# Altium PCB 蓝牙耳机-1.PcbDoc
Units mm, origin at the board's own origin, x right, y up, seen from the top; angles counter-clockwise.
Board outline 16.51 x 36.18 mm, 2 copper layers (Top Layer, Bottom Layer); 36 components, 36 nets, 115 pads, 134 vias.
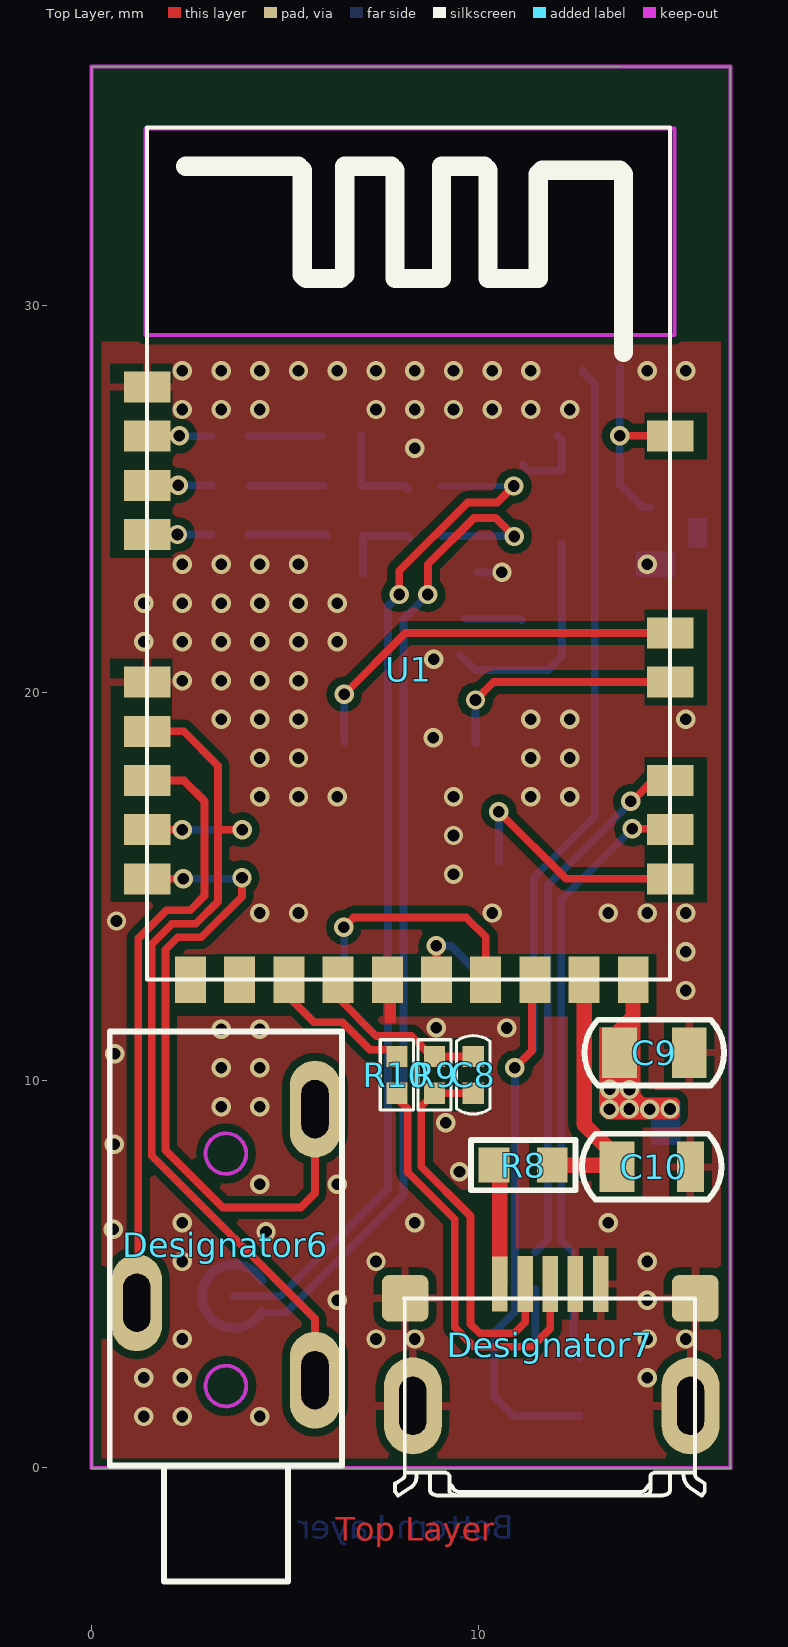
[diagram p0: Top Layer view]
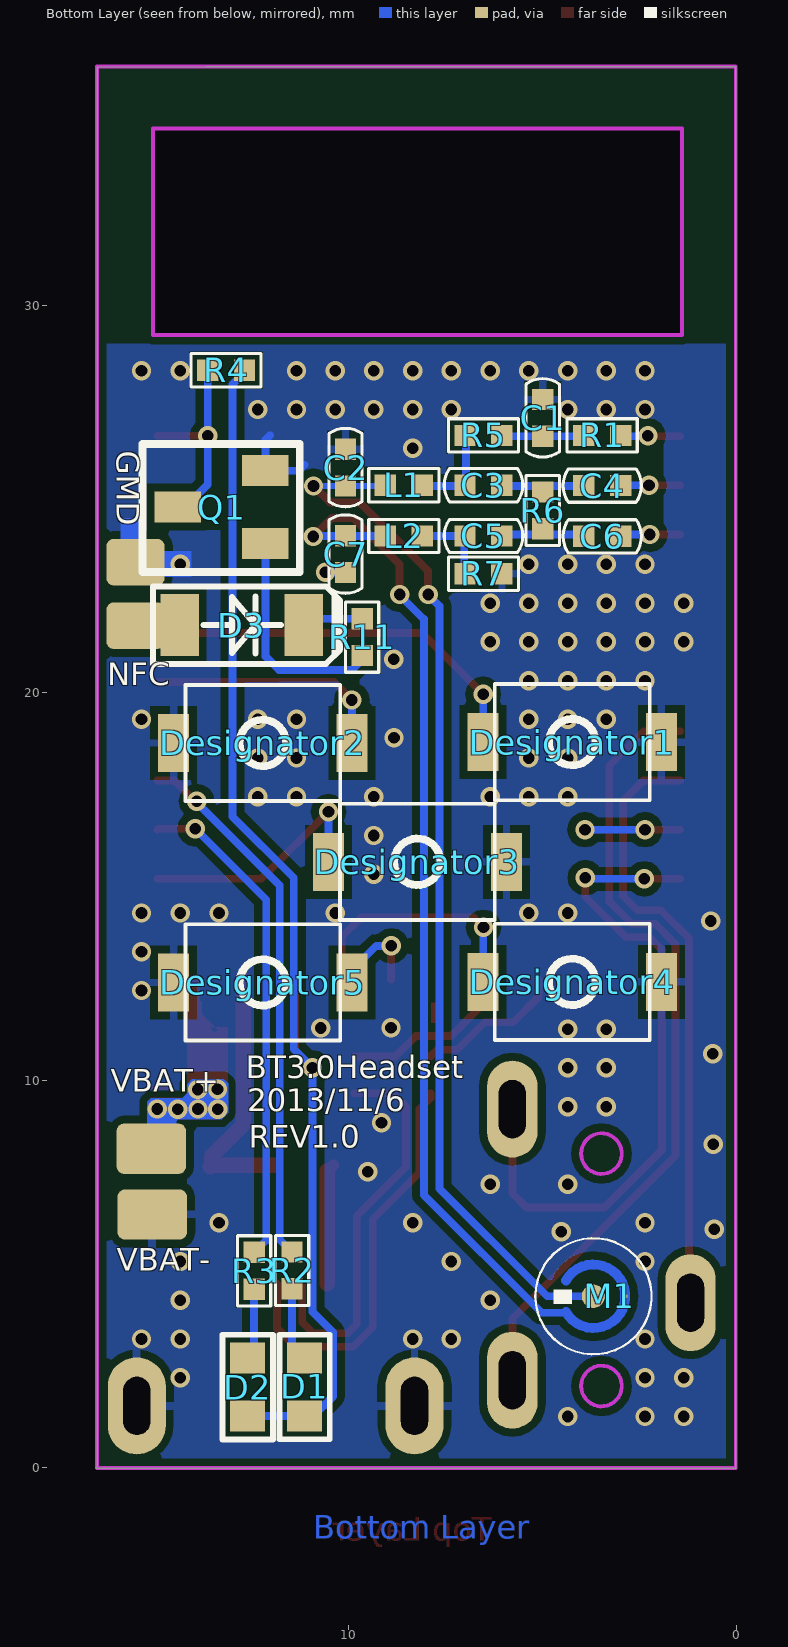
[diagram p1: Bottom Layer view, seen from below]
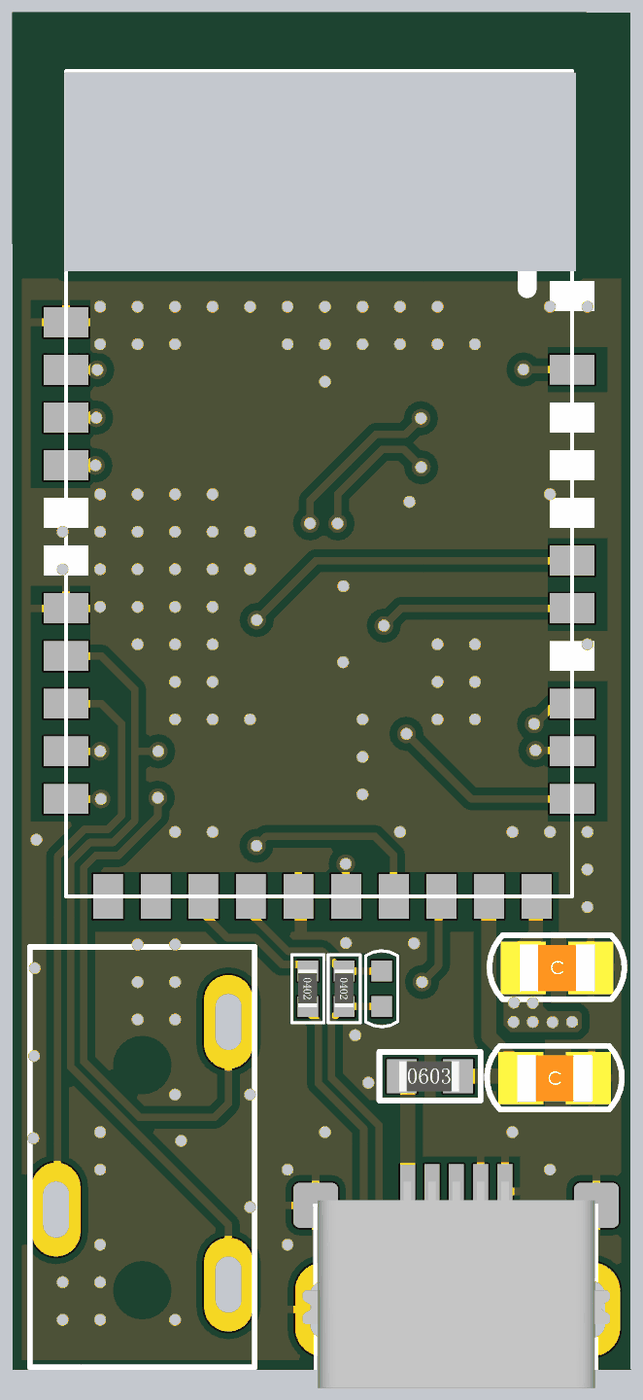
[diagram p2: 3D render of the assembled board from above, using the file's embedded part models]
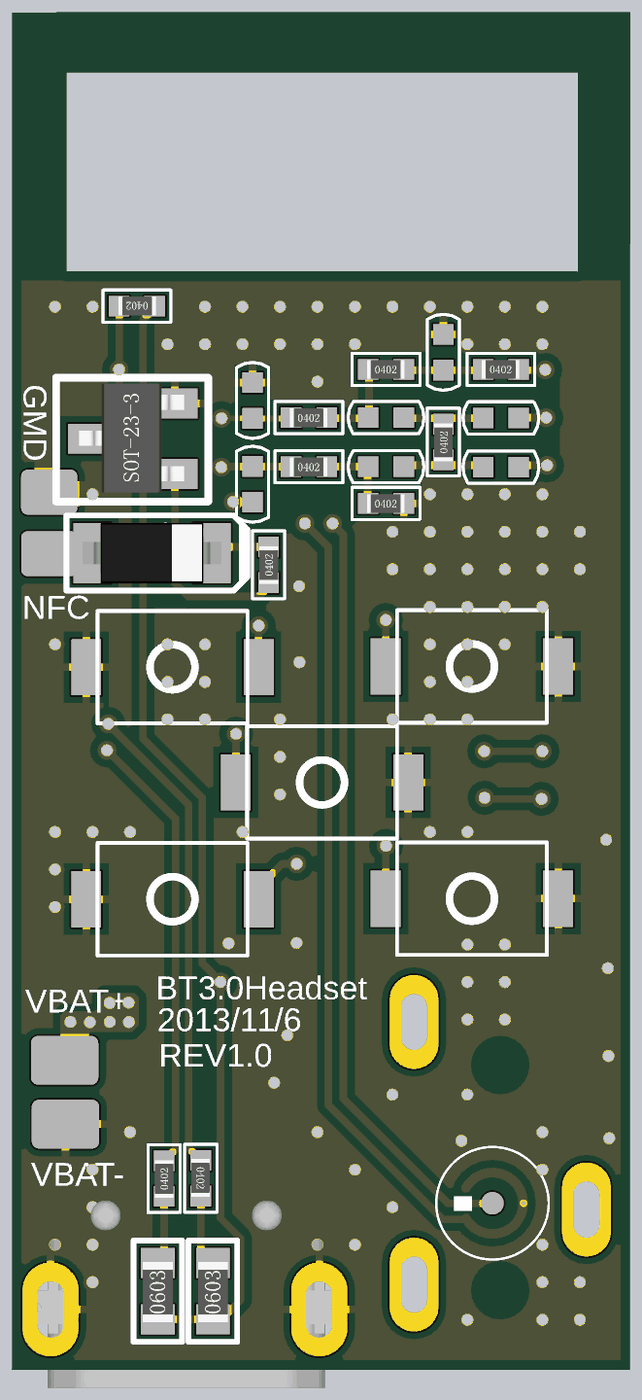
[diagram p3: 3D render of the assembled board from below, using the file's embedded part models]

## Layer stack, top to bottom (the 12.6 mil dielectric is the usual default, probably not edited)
Top Solder: solder mask 0.0102, Solder Resist, Dk 3.5
Top Layer: signal copper 0.0356
Dielectric1: dielectric 0.32, FR-4, Dk 4.8
Bottom Layer: signal copper 0.0356
Bottom Solder: solder mask 0.0102, Solder Resist, Dk 3.5

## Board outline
13.687,36.165 0.006,36.166 0.01,29.208 0.01,-0.019 16.506,-0.019 16.52,-0.005 16.492,0.023 16.494,36.156
cut-out: 15.045,34.559 1.406,34.559 1.388,34.542 1.406,34.524 1.406,29.234 1.428,29.256 15.054,29.256 15.049,29.261 15.049,34.551

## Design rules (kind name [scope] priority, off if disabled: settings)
Clearance "Stitching GND" [IsStitchingVia and InNet('GND') vs (IsVia and (Not IsStitchingVia)) Or IsPad] p1: gap=0.127
Clearance Clearance_1 [InPolygon] p2: gap=0.2
Clearance [All] p3: gap=0.15
PolygonConnect PolygonConnect_1 [IsVia] p1: connectstyle=Direct reliefconductorwidth=0.254 reliefentries=4 polygonreliefangle="90 Angle" airgapwidth=0.254
PolygonConnect [All] p2: connectstyle=Relief reliefconductorwidth=0.2 reliefentries=4 polygonreliefangle="90 Angle" airgapwidth=0.2
RoutingVias [All] p1: holewidth=0.3 width=0.5 viastyle="Through Hole" minholewidth=0.3 minwidth=0.5 maxholewidth=0.3 maxwidth=0.5
SolderMaskExpansion [All] p1: expansion=0.05
Width [All] p1: maxlimit=3 minlimit=0.1 preferedwidth=0.2
29 further rules are at their usual default settings.

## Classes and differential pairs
component class Sheet1: BT1 C1 C2 C3 C4 C5 C6 C7 C8 C9 D1 D2 D3 L1 L2 Q1 R1 R2 R3 R4 R5 R6 R7 R8 R9 R10 R11 U1

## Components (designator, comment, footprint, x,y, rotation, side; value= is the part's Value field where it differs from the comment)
C1 "2.2UF" 0402C 4.994,27.101 r90 bottom
C2 "100PF" 0402C 10.084,25.818 r270 bottom
C3 "0.1U" 0402C 6.521,25.362 r180 bottom
C4 "0.022U" 0402C 3.456,25.352 r180 bottom
C5 "0.1U" 0402C 6.521,24.051 r180 bottom
C6 "0.022U" 0402C 3.456,24.041 r180 bottom
C7 "100PF" 0402C 10.084,23.585 r270 bottom
C8 "1UF" 0402C 9.861,10.138 r270 top
C9 "10UF" 0805C#1 14.537,10.712 r0 top
C10 "10UF" 0805C#2 14.471,7.768 r0 top
D1 "BLED" 0603 11.141,2.079 r90 bottom
D2 "RLED" 0603 12.61,2.077 r90 bottom
D3 "1N5817" SOD123 12.764,21.75 r180 bottom
Designator1 "Comment" SW-SMD-2 4.229,18.728 r0 bottom
Designator2 "Comment" SW-SMD-2 12.219,18.708 r180 bottom
Designator3 "Comment" SW-SMD-2 8.229,15.638 r0 bottom
Designator4 "Comment" SW-SMD-2 4.229,12.539 r0 bottom
Designator5 "Comment" SW-SMD-2 12.219,12.525 r180 bottom
Designator6 "Comment" jack-3 3.475,0.054 r90 top
Designator7 "Comment" "Micro USB-B" 11.891,2.328 r180 top
L1 "15NH" 0402 8.579,25.362 r180 bottom
L2 "15NH" 0402 8.579,24.051 r180 bottom
M1 "" MIC3 3.681,4.422 r0 bottom
Q1 "2N3904" SOT-23 13.281,24.798 r90 bottom
R1 "100R" 0402 3.456,26.647 r180 bottom
R2 "1K" 0402 11.463,5.089 r270 bottom
R3 "1K" 0402 12.443,5.079 r90 bottom
R4 "10K" 0402 13.169,28.332 r0 bottom
R5 "1K" 0402 6.521,26.647 r180 bottom
R6 "100K" 0402 4.994,24.71 r90 bottom
R7 "1K" 0402 6.521,23.073 r180 bottom
R8 "2R" 0603 11.151,7.808 r0 top
R9 "5.1K" 0402 8.861,10.138 r270 top
R10 "5.1K" 0402 7.891,10.138 r270 top
R11 "1K" 0402 9.655,21.439 r90 bottom
U1 "BCM20771" BT2771 1.442,34.598 r0 top locked

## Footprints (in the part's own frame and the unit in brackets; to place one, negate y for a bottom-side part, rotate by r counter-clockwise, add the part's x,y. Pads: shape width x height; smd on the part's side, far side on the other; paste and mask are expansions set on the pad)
0402 [mm]
  rect 0.55x0.55 smd: 1(-0.475,0) 2(0.475,0)
  silkscreen extent -0.9,-0.43 0.9,0.43, body extent -0.51,-0.25 0.49,0.25, height 0.35
0402C [mm]
  rect 0.55x0.55 smd: 1(-0.475,0) 2(0.475,0)
  silkscreen extent -1.01,-0.43 1.01,0.43, body extent -0.47,-0.28 0.49,0.27, height 0.5
0603 [mm]
  rect 0.8x0.9 smd: 1(-0.75,0) 2(0.75,0)
  silkscreen extent -1.35,-0.65 1.35,0.65, body extent -0.82,-0.4 0.78,0.4, height 0.45
0805C#1 [mm]
  rect 0.9x1.3 smd: 1(-0.9,0) 2(0.9,0)
  silkscreen extent -1.8,-0.85 1.8,0.85, body extent -1.49,-0.72 1.51,0.68, height 0.93
0805C#2 [mm]
  rect 0.9x1.3 smd: 1(-0.9,0)
  rect 0.7x1.3 smd: 2(0.995,-0.007)
  silkscreen extent -1.8,-0.85 1.8,0.85, body extent -1.49,-0.72 1.51,0.68, height 0.93
BT2771 [mm] "U?"
  rect 1.2x0.8 smd mask+0.05: 1(0,-6.7) 2(0,-7.97) 3(0,-9.24) 4(0,-10.51) 7(0,-14.32) 8(0,-15.59) 9(0,-16.86) 10(0,-18.13) 11(0,-19.4) 22(13.5,-19.4) 23(13.5,-18.13) 24(13.5,-16.86) 26(13.5,-14.32) 27(13.5,-13.05) 31(13.5,-7.96)
  rect 1.2x0.8 on Top Overlay mask+0.05: 5(0,-11.78) 6(0,-13.05) 25(13.5,-15.59) 28(13.5,-11.78) 29(13.5,-10.51) 30(13.5,-9.24) 32(13.5,-6)
  rect 0.8x1.2 smd mask+0.05: 12(1.12,-22) 13(2.39,-22) 14(3.66,-22) 15(4.93,-22) 16(6.2,-22) 17(7.47,-22) 18(8.74,-22) 19(10.01,-22) 20(11.28,-22) 21(12.55,-22)
  silkscreen extent 0,-22 13.5,0
jack-3 [mm]
  oval 2.5x1.3 hole 0.7 slot 1.5 at 0 deg: 1(2.2,-2.3) 2(4.2,2.3) 3(9.2,-2.3)
  Keep-Out Layer circle w0.1: c8.05,0 r0.525
  Keep-Out Layer circle w0.1: c2.05,0 r0.525
  silkscreen extent -3,-3 11.2,3
MIC3 [mm]
  round 0.6 smd: 1(0,0)
  round 0.1 smd mask+0.05: 2(-0.83,0)
  Top Layer lines w0.254: 0.71,0.41 ccw(c0,0) 0.71,-0.41
  silkscreen extent -1.5,-1.5 1.5,1.5
"Micro USB-B" [mm]
  rrect30% 1.2x1.2 smd: 0(-3.7,-2.04) 1(3.79,-2.04)
  rect 0.4x1.42 smd: 1(1.34,-2.41)
  rect 0.4x1.45 smd: 2(0.69,-2.41) 3(0.04,-2.41) 4(-0.61,-2.41) 5(-1.26,-2.41)
  oval 1.5x2.5 hole 0.7 slot 1.5 at 90 deg: 5(-3.581,0.736) 5(3.589,0.736)
  silkscreen extent -3.95,-2.04 4.05,3.05, body extent -4.06,-2.67 4.14,2.83, height 2.4
SOD123 [mm]
  rect 1x1.6 smd: 1(-1.6,0) 2(1.6,0)
  silkscreen extent -2.29,-1 2.54,1, body extent -1.85,-0.8 1.85,0.8, height 1.27
SOT-23 [mm] "Q?"
  rect 0.8x1.2 smd: 1(-0.94,-1.13) 2(0.94,-1.13) 3(0,1.13)
  silkscreen extent -1.68,-2.02 1.63,2.04, body extent -1.43,-1.37 1.47,1.43, height 1.2
SW-SMD-2 [mm]
  rect 0.8x1.5 smd: 1(-2.3,0) 2(2.3,0)
  silkscreen extent -2,-1.5 2,1.5

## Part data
C1 C2 C3 C4 C5 C6 C7 C8 C9: library part CAP, "Capacitor"
D1 D2: library part LED
D3: library part D1, "Diode"
L1 L2: library part INDUCTOR2_1
M1: library part MICROPHONE1, "Microphone"
Q1: "NPN General Purpose Amplifier"
R1 R2 R3 R4 R5 R6 R7 R8 R9 R10 R11: library part R
U1: library part BT20771

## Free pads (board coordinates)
  rrect30% 1.5x1.2 smd far side: 0(15.506,21.733) 1(15.507,23.373)
  rrect30% 1.8x1.3 smd far side: 2(15.073,6.53) 3(15.096,8.231)

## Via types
v1: diameter 0.5, hole 0.3, Top Layer to Bottom Layer, tented both sides, 134 vias

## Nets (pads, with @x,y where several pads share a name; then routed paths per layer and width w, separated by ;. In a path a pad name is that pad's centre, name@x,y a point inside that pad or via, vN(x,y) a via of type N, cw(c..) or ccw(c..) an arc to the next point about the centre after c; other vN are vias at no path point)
GND: C1.2 C2.1 C7.2 C9.2 C10.2 Designator1.1 Designator2.1 Designator3.1 Designator4.1 Designator5.1 Designator7.0 Designator7.1@8.101,4.368 Designator7.4 Designator7.5 pad.1 pad.2 Q1.2 R7.2 U1.1 U1.7 U1.16 | length 2.7
  Bottom Layer w0.2: C7.2@9.974,23.11 10.596,23.11 v1(10.602,23.116) ; 11.144,25.888 11.294,25.738 Q1.2 12.151,26.536 12.035,26.652
  other v1: 1.35,1.317 2.35,1.317 4.35,1.317 1.35,2.317 2.35,2.317 14.35,2.317 2.35,3.317 7.35,3.317 8.35,3.317 14.35,3.317 15.35,3.317 6.35,4.317 14.35,4.317 2.35,5.317 7.35,5.317 14.35,5.317 4.51,6.087 0.566,6.154 2.35,6.317 8.35,6.317 13.35,6.317 4.35,7.317 6.35,7.317 9.506,7.633 0.589,8.347 9.155,8.898 3.35,9.317 4.35,9.317 3.35,10.317 4.35,10.317 0.604,10.686 3.35,11.317 4.35,11.317 8.909,11.358 10.723,11.348 15.35,12.317 15.35,13.317 0.65,14.109 4.35,14.317 5.35,14.317 10.35,14.317 13.35,14.317 14.35,14.317 15.35,14.317 9.35,15.317 9.35,16.317 4.35,17.317 5.35,17.317 6.35,17.317 9.35,17.317 11.35,17.317 12.35,17.317 4.35,18.317 5.35,18.317 11.35,18.317 12.35,18.317 8.832,18.842 3.35,19.317 4.35,19.317 5.35,19.317 11.35,19.317 12.35,19.317 15.35,19.317 2.35,20.317 3.35,20.317 4.35,20.317 5.35,20.317 8.84,20.868 1.35,21.317 2.35,21.317 3.35,21.317 4.35,21.317 5.35,21.317 6.35,21.317 1.35,22.317 2.35,22.317 3.35,22.317 4.35,22.317 5.35,22.317 6.35,22.317 2.35,23.317 3.35,23.317 4.35,23.317 5.35,23.317 14.35,23.317 8.35,26.317 2.35,27.317 3.35,27.317 4.35,27.317 7.35,27.317 8.35,27.317 9.35,27.317 10.35,27.317 11.35,27.317 12.35,27.317 2.35,28.317 3.35,28.317 4.35,28.317 5.35,28.317 6.35,28.317 7.35,28.317 8.35,28.317 9.35,28.317 10.35,28.317 11.35,28.317 14.35,28.317 15.35,28.317
LED1: R2.1 U1.24 | length 13.9
  Top Layer w0.2: v1@13.926,17.165 14.499,17.738 14.587,17.738 U1.24
  Bottom Layer w0.2: R2.1 11.783,5.883 11.783,15.028 13.924,17.169 v1@13.939,17.169
  other v1: 13.929,17.197
LED2: R3.2 U1.23 | length 12.8
  Top Layer w0.2: v1(13.965,16.492) 14.918,16.492 U1.23
  Bottom Layer w0.2: R3.2 12.133,5.864 12.133,14.66 v1(13.965,16.492)
M+: C2.2 L1.1 M1.1 | length 27
  Top Layer w0.2: v1@7.953,22.54 7.953,23.153 9.716,24.915 10.482,24.915 v1(10.91,25.343)
  Bottom Layer w0.15: L1.1@9.019,25.338 C2.2@9.978,25.338 ; C2.2@9.978,25.343 v1(10.91,25.343)
  Bottom Layer w0.2: M1.1 4.874,4.422 5.029,4.577 ; 5.032,4.575 7.66,7.202 7.66,22.243 v1@7.96,22.543
  other v1: 7.95,22.54
M-: C7.1 L2.1 M1.2 | length 26.3
  Top Layer w0.2: v1@8.69,22.535 8.69,23.324 9.881,24.515 10.439,24.515 v1(10.916,24.038)
  Bottom Layer w0.2: 4.392,4.043 4.392,4.012 4.392,3.995 4.393,3.993 5.016,3.993 8.06,7.037 8.06,21.904 v1@8.693,22.537 ; L2.1 v1@10.912,24.051
  other v1: 8.685,22.54
MIC+: C4.2 U1.3 | length 1.7
  Top Layer w0.2: U1.3 v1(2.248,25.358)
  Bottom Layer w0.2: v1(2.248,25.358) 2.251,25.362 C4.2@3.111,25.362
MIC-: C6.2 U1.4 | length 1.7
  Top Layer w0.2: U1.4 v1(2.227,24.088)
  Bottom Layer w0.2: v1@2.228,24.089 C6.2@3.111,24.089
MIC-BLAS: R1.2 U1.2 | length 1.7
  Top Layer w0.2: U1.2 2.269,26.628 v1(2.275,26.635)
  Bottom Layer w0.2: v1(2.275,26.635) 2.282,26.628 R1.2@3.106,26.628
NetC1_1: C1.1 R1.1 R5.2 | length 1.9
  Bottom Layer w0.2: R1.1@4.056,26.628 5.945,26.628 R5.2@5.948,26.624
NetC3_1: C3.1 L1.2 R5.1 | length 2.5
  Bottom Layer w0.2: R5.1@6.971,26.647 6.971,25.368 6.996,25.343 8.096,25.343 L1.2@8.175,25.265
NetC3_2: C3.2 C4.1 R6.2 | length 1.9
  Bottom Layer w0.15: C4.1@4.061,25.362 C4.1@4.08,25.343
  Bottom Layer w0.2: C4.1@4.08,25.343 C3.2@6.002,25.343
NetC5_1: C5.1 L2.2 R7.1 | length 2.2
  Bottom Layer w0.2: C5.1@6.983,24.018 7.015,23.987 R7.1@7.015,23.073 ; C5.1@7.015,24.051 8.142,24.051 L2.2@8.206,23.987
NetC5_2: C5.2 C6.1 R6.1 | length 2
  Bottom Layer w0.2: C6.1@4.061,24.089 6.027,24.089 C5.2@6.065,24.051
NetC8_2: C8.2 Designator7.2 R9.2 | length 10.2
  Top Layer w0.2: C8.2 R9.2 8.521,9.323 8.521,7.765 9.791,6.495 9.791,3.703 10.026,3.468 10.921,3.468 11.201,3.748 Designator7.2
NetD1_2: D1.2 R2.2 | length 1.5
  Bottom Layer w0.2: D1.2@11.463,3.152 R2.2
NetD2_2: D2.2 R3.1 | length 1.8
  Bottom Layer w0.2: R3.1 12.443,2.993 D2.2
NetD3_1: D3.1 pad.0
NetD3_2: D3.2 R11.2 | length 1.5
  Bottom Layer w0.2: R11.2 11.063,21.914 D3.2@11.105,21.873
NetJp1_3: Designator7.3 R10.2 | length 10.7
  Top Layer w0.2: R10.2 7.891,9.538 8.171,9.258 8.171,7.62 9.381,6.41 9.381,3.618 9.881,3.118 11.381,3.118 11.851,3.588 Designator7.3
NetQ1_1: Q1.1 R11.1 | length 5.8
  Bottom Layer w0.2: R11.1@9.528,20.973 9.909,20.592 11.802,20.592 12.151,20.941 Q1.1
NFC: Q1.3 R4.2 U1.31 | length 5.3
  Top Layer w0.2: v1(13.644,26.643) 13.649,26.638 U1.31
  Bottom Layer w0.2: R4.2@13.649,28.401 13.642,28.394 13.642,25.381 14.224,24.798 Q1.3
ON/OFF: Designator3.2 U1.22 | length 6.4
  Top Layer w0.2: v1(10.523,16.933) 12.258,15.198 U1.22
  Bottom Layer w0.2: v1(10.523,16.933) 10.523,15.644 Designator3.2
RX: R10.1 U1.14 | length 3.9
  Top Layer w0.2: U1.14 5.102,12.147 5.751,11.498 6.486,11.498 7.196,10.788 7.716,10.788 R10.1
SL+: Designator6.3 U1.11 | length 17.5
  Top Layer w0.2: U1.11 v1(2.371,15.198) ; v1(3.891,15.228) 3.891,14.738 2.841,13.688 2.231,13.688 1.912,13.369 1.912,8.199 3.397,6.714 5.41,6.714 5.775,7.079 Designator6.3
  Bottom Layer w0.2: v1(2.371,15.198) 3.891,15.198 v1(3.891,15.228)
SL-: 
SR+: Designator6.2 U1.9 | length 15.8
  Top Layer w0.2: Designator6.2@1.02,4.248 1.212,4.44 1.212,13.659 1.941,14.388 2.551,14.388 2.921,14.758 2.921,17.208 2.391,17.738 U1.9
SR-: Designator6.1 U1.8 U1.10 | length 24
  Top Layer w0.2: U1.10 2.371,16.468 v1(2.351,16.468) ; U1.8 2.383,19.008 3.271,18.12 3.271,16.496 ; v1(3.901,16.468) 3.299,16.468 3.271,16.496 ; Designator6.1 5.775,3.841 1.562,8.054 1.562,13.514 2.086,14.038 2.696,14.038 3.271,14.613 3.271,16.496
  Bottom Layer w0.2: v1(2.351,16.468) v1(3.901,16.468)
TX: C8.1 R9.1 U1.15 | length 4.6
  Top Layer w0.2: U1.15 6.372,12.127 7.361,11.138 8.27,11.138 8.795,10.613 C8.1
USB-5V: Designator7.1@10.551,4.738 R8.1 | length 3.1
  Top Layer w0.3: R8.1 R8.1@10.551,7.658
  Top Layer w0.4: Designator7.1@10.551,4.738 R8.1@10.551,7.658
VBAT: C9.1 pad.3 U1.21 | length 2.3
  Top Layer w0.3: C9.1@13.626,10.475 13.626,11.195 13.992,11.561 U1.21
  other v1: 13.38,9.252 13.891,9.255 14.42,9.246 14.941,9.257 13.39,9.769 13.894,9.76
VDD-USB: C10.1 R8.2 U1.20 | length 6.8
  Top Layer w0.4: R8.2 C10.1@13.531,7.808 ; U1.20 12.722,8.858 13.531,8.049 C10.1@13.531,7.808 ; C10.1 C10.1@13.531,7.808
VOL+: Designator1.2 U1.27 | length 10.3
  Top Layer w0.2: v1(6.529,19.966) 8.111,21.548 U1.27
  Bottom Layer w0.2: Designator1.2 v1(6.529,19.966)
VOL-: Designator2.2 U1.26 | length 6.3
  Top Layer w0.2: v1(9.919,19.816) 10.381,20.278 U1.26
  Bottom Layer w0.2: Designator2.2 v1(9.919,19.816)
VOUT: D1.1 D2.1 R4.1 U1.19 | length 32.6
  Top Layer w0.2: v1(10.937,10.317) 11.379,10.758 11.379,12.524 U1.19
  Bottom Layer w0.2: v1@10.905,10.289 11.42,10.804 11.42,15.225 13.001,16.806 13.001,27.971 12.694,28.277 R4.1 ; v1(10.937,10.317) 10.937,4.022 10.406,3.491 10.406,1.834 10.914,1.327 D2.1
¤U¤@¦±: Designator4.2 U1.18 | length 6.5
  Top Layer w0.2: v1(6.521,13.948) 6.771,14.198 9.683,14.198 10.182,13.699 U1.18
  Bottom Layer w0.2: v1(6.521,13.948) 6.529,13.94 Designator4.2
¤W¤@¦±: Designator5.2 U1.17 | length 2.5
  Top Layer w0.2: v1(8.901,13.467) 8.912,13.456 U1.17
  Bottom Layer w0.2: v1(8.901,13.467) 9.286,13.467 9.919,12.834 Designator5.2
pads on no net: U1.5 U1.6 U1.12 U1.13 U1.25 U1.28 U1.29 U1.30 U1.32

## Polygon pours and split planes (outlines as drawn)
GND on Bottom Layer "Top Layer-No Net" (solid, remove dead copper, pour order 9): 16.779,29.016 -2.095,29.016 -2.686,28.425 -1.824,27.564 -1.824,-1.345 19.341,-1.345 19.62,-1.625 16.793,1.203 16.793,29.031
GND on Top Layer "Top Layer-No Net" (solid, remove dead copper, pour order 11): 17.683,29.062 -0.363,29.062 -1.304,28.121 -2.28,27.145 -2.28,-2.054 19.322,-2.054 19.659,-2.391 18.225,-0.957 18.225,28.915

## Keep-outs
Keep-Out Layer:
  lines w0.1: 15.056,29.247 15.056,34.571 1.393,34.571 1.393,29.245 15.058,29.245 ; 0.01,-0.012 16.501,-0.012 16.501,36.175 0.01,36.175 0.01,-0.012

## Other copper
Top Layer:
  rectangle net GND: 7.569,11.482 7.872,12.007
  rectangle net GND: 14.559,9.749 15.197,9.862
  region net VBAT: 13.492,11.238 13.698,11.363 13.121,11.362 13.12,11.286 13.12,9.156 13.289,8.987 15.104,8.987 15.199,9.083 15.199,9.46 15.114,9.546 14.281,9.546 14.17,9.656 14.17,12.047 14.104,12.113 14.026,12.035 13.792,12.035 13.792,11.71 13.37,11.287
  pour cut-out: 14.22,8.598 14.22,8.836 14.14,8.916 14.07,8.847 14.07,8.62 14.106,8.584
  pour cut-out: 10.2,7.169 10.366,7.002 10.366,6.76 10.157,6.55 9.538,7.169
  text "Top Layer" at 6.311,-1.893 h0.6
Bottom Layer:
  rectangle net GND: 14.058,22.996 15.075,23.659
  rectangle net GND: 15.419,23.751 15.896,24.515
  region net VBAT: 15.209,8.331 15.209,9.439 15.112,9.536 14.295,9.536 14.173,9.658 14.173,9.9 14.047,10.025 13.227,10.025 13.118,9.915 13.118,9.154 13.283,8.989 14.407,8.989 14.451,8.945 14.451,8.362 14.486,8.328
  pour cut-out: 1.877,26.751 1.877,24.07 2.088,23.86 2.11,23.882 2.464,23.882 2.758,24.175 2.758,26.724 2.492,26.989 2.099,26.989 1.872,26.762
  pour cut-out: 11.267,25.336 12.976,25.336 13.003,25.309 13.003,25.095 11.34,25.095 11.249,25.186
  pour cut-out: 10.707,3.209 10.707,0.729 10.713,0.723 13.255,0.723 13.261,0.718 13.261,3.428 13.255,3.434 10.91,3.434 10.713,3.237
  pour cut-out: 11.639,20.292 12.971,20.292 13.073,20.393 12.982,20.483 12.982,20.797 12.181,20.797 12.106,20.872
  pour cut-out: 13.698,24.198 13.03,24.198 12.911,24.317 13.125,24.531 13.957,24.531
  text "Bottom Layer" at 10.913,-1.846 h0.6

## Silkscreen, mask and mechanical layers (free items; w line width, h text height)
Top Overlay:
  text "T:0.8mm" at 7.738,37.468 h0.6
Bottom Overlay:
  text "GMD" at 16.19,26.25 h1 r90
  text "NFC" at 16.23,20 h1
  text "BT3.0Headset" at 12.663,9.857 h1
  text "VBAT+" at 16.15,9.51 h1
  text "2013/11/6" at 12.625,9.01 h1
  text "REV1.0" at 12.587,8.062 h1
  text "VBAT-" at 15.99,4.89 h1
Drill Drawing:
  text ".Legend" at 7.76,36.71 h0.6

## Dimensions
16.501,36.175 to 16.501,-0.012 on Keep-Out Layer
16.501,36.175 to 0.01,36.175 on Keep-Out Layer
